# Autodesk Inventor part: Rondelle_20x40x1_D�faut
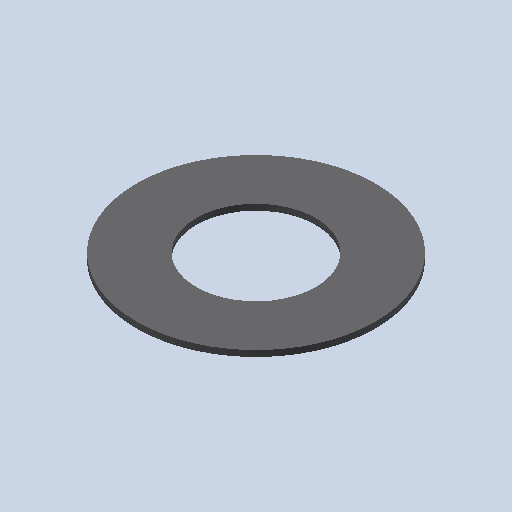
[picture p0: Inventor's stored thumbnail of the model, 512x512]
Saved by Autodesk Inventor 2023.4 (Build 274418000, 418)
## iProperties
Created: 2011-01
Part Number: Rondelle_20x40x1_D�faut
Document SubType Name: Modeling
Designer: eric
Density: 1 g/cm^3
Mass: 0.942478 g
Surface Area: 20.7345 cm^2
Volume: 0.942478 cm^3
Material: Générique
Appearance: Yellow
Author: eric
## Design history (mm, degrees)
feature "Base1"
node "Corps solides"
node "Corps surfaciques"
node "Solide1"
